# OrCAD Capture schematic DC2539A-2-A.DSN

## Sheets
1 PAGE2: size Custom
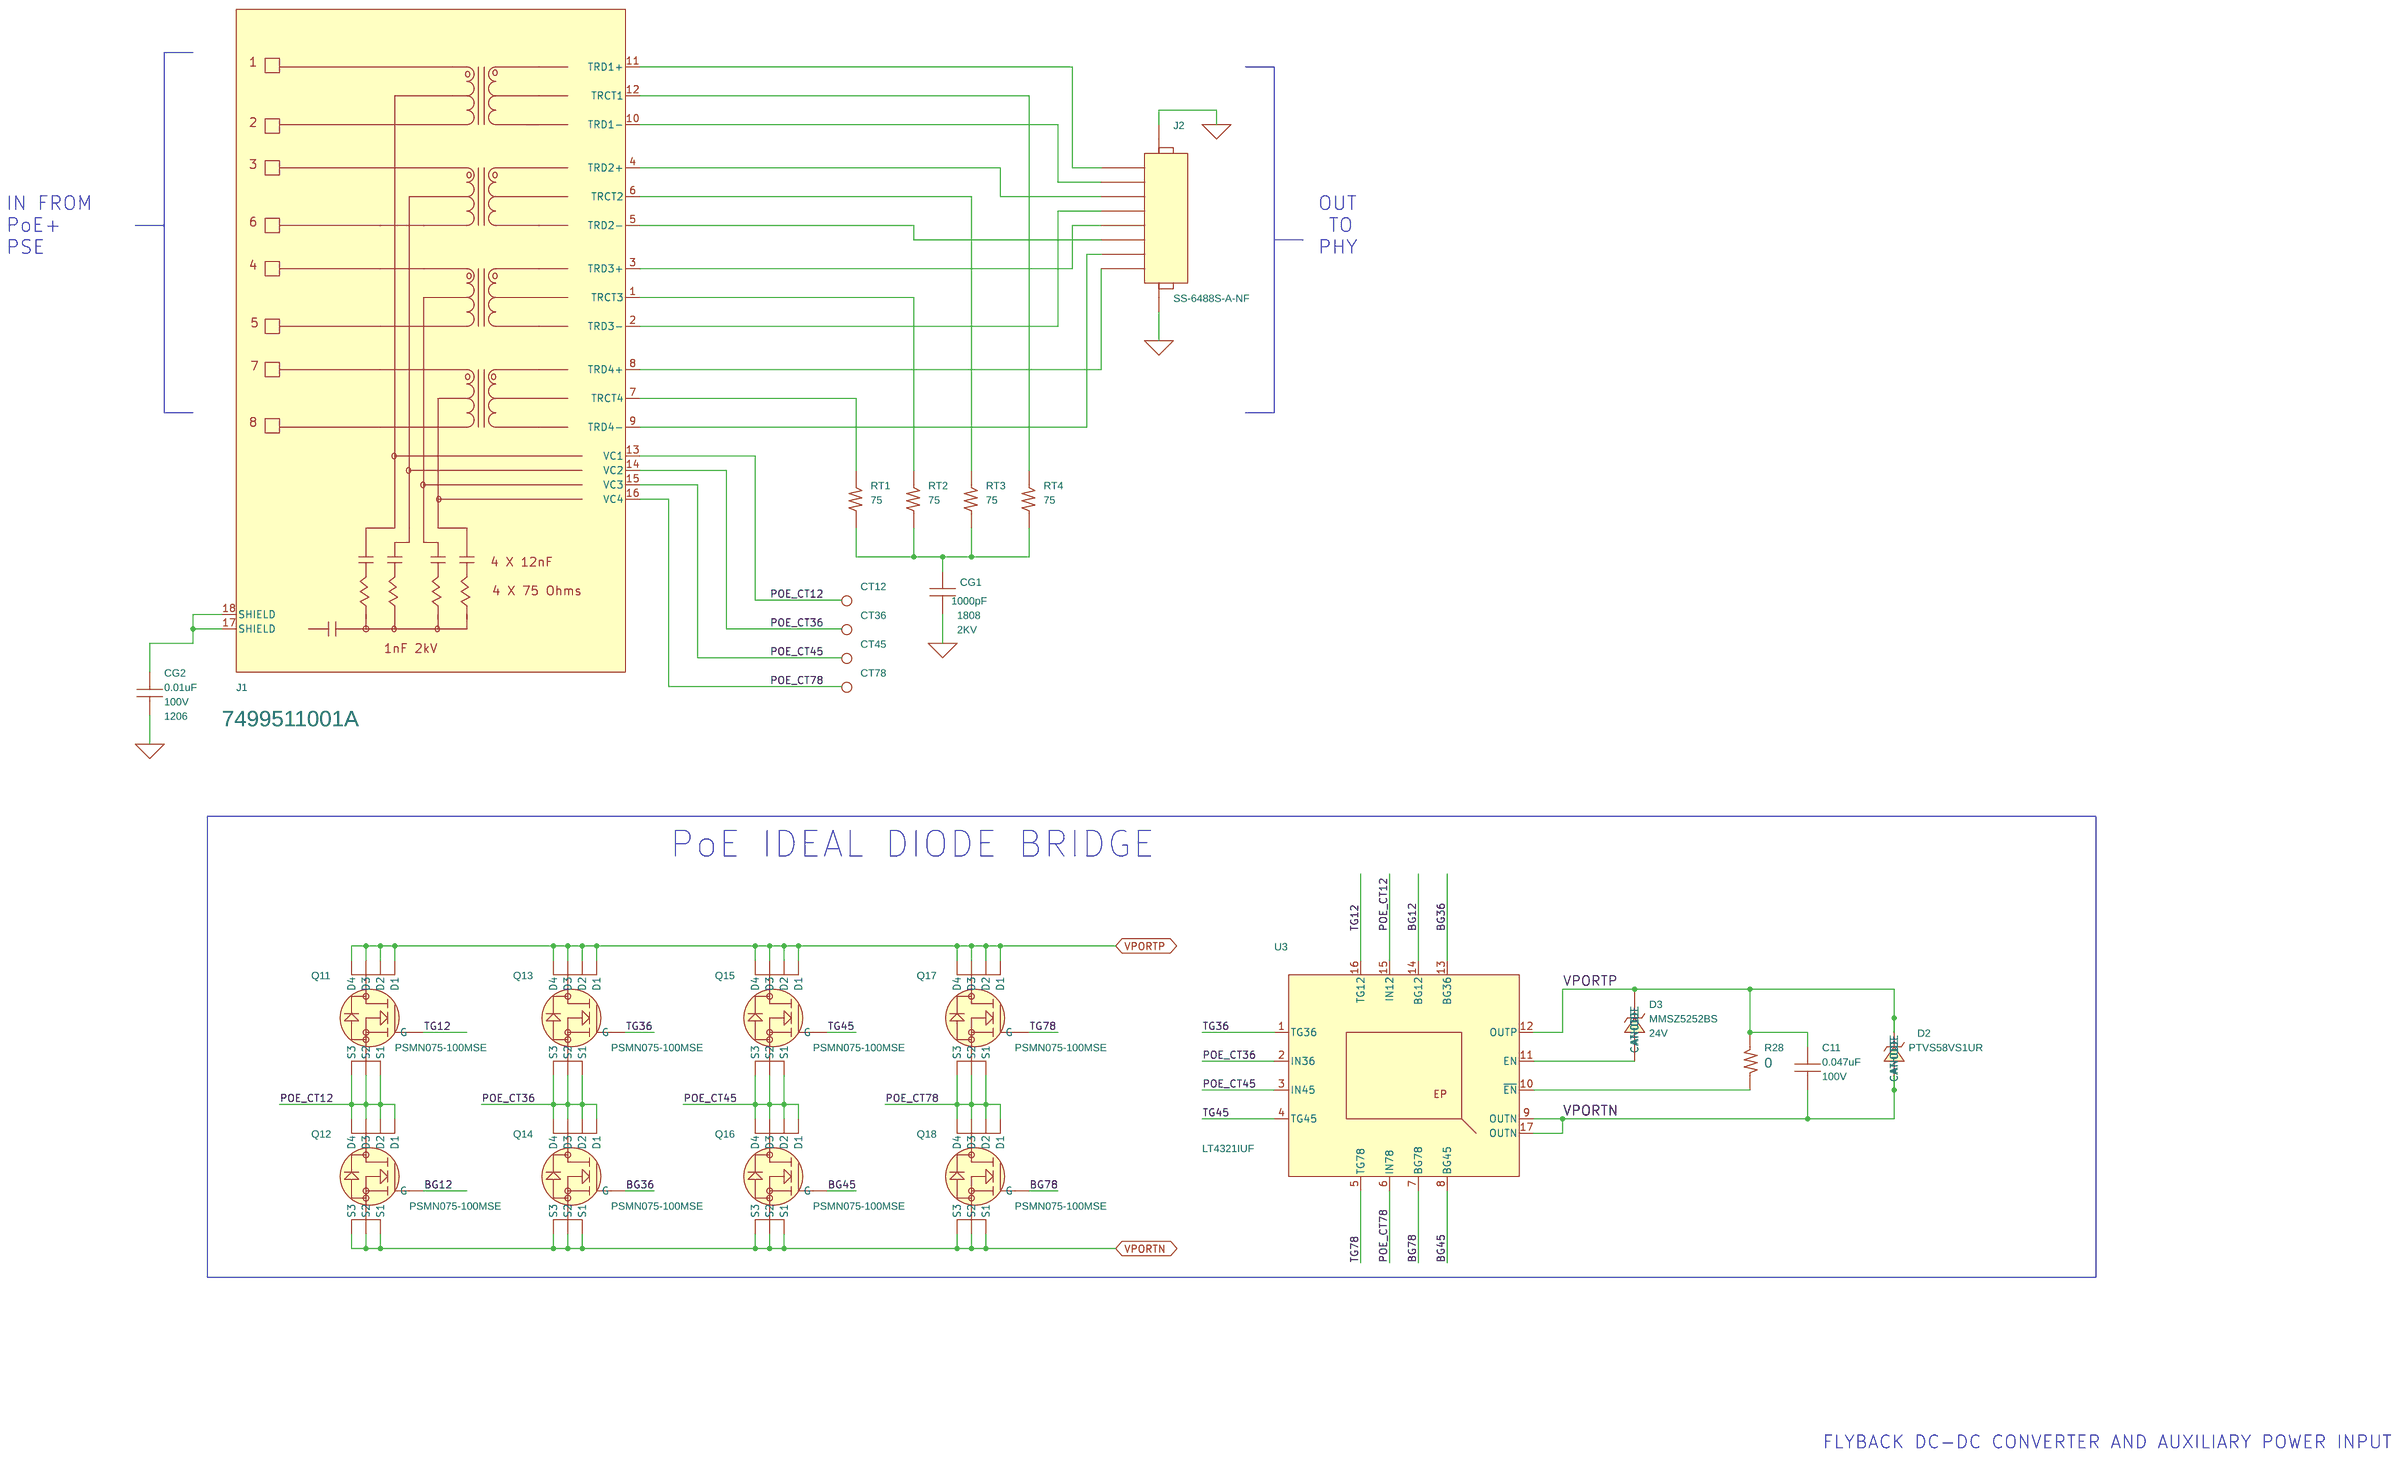
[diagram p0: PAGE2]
2 PAGE1: size Custom
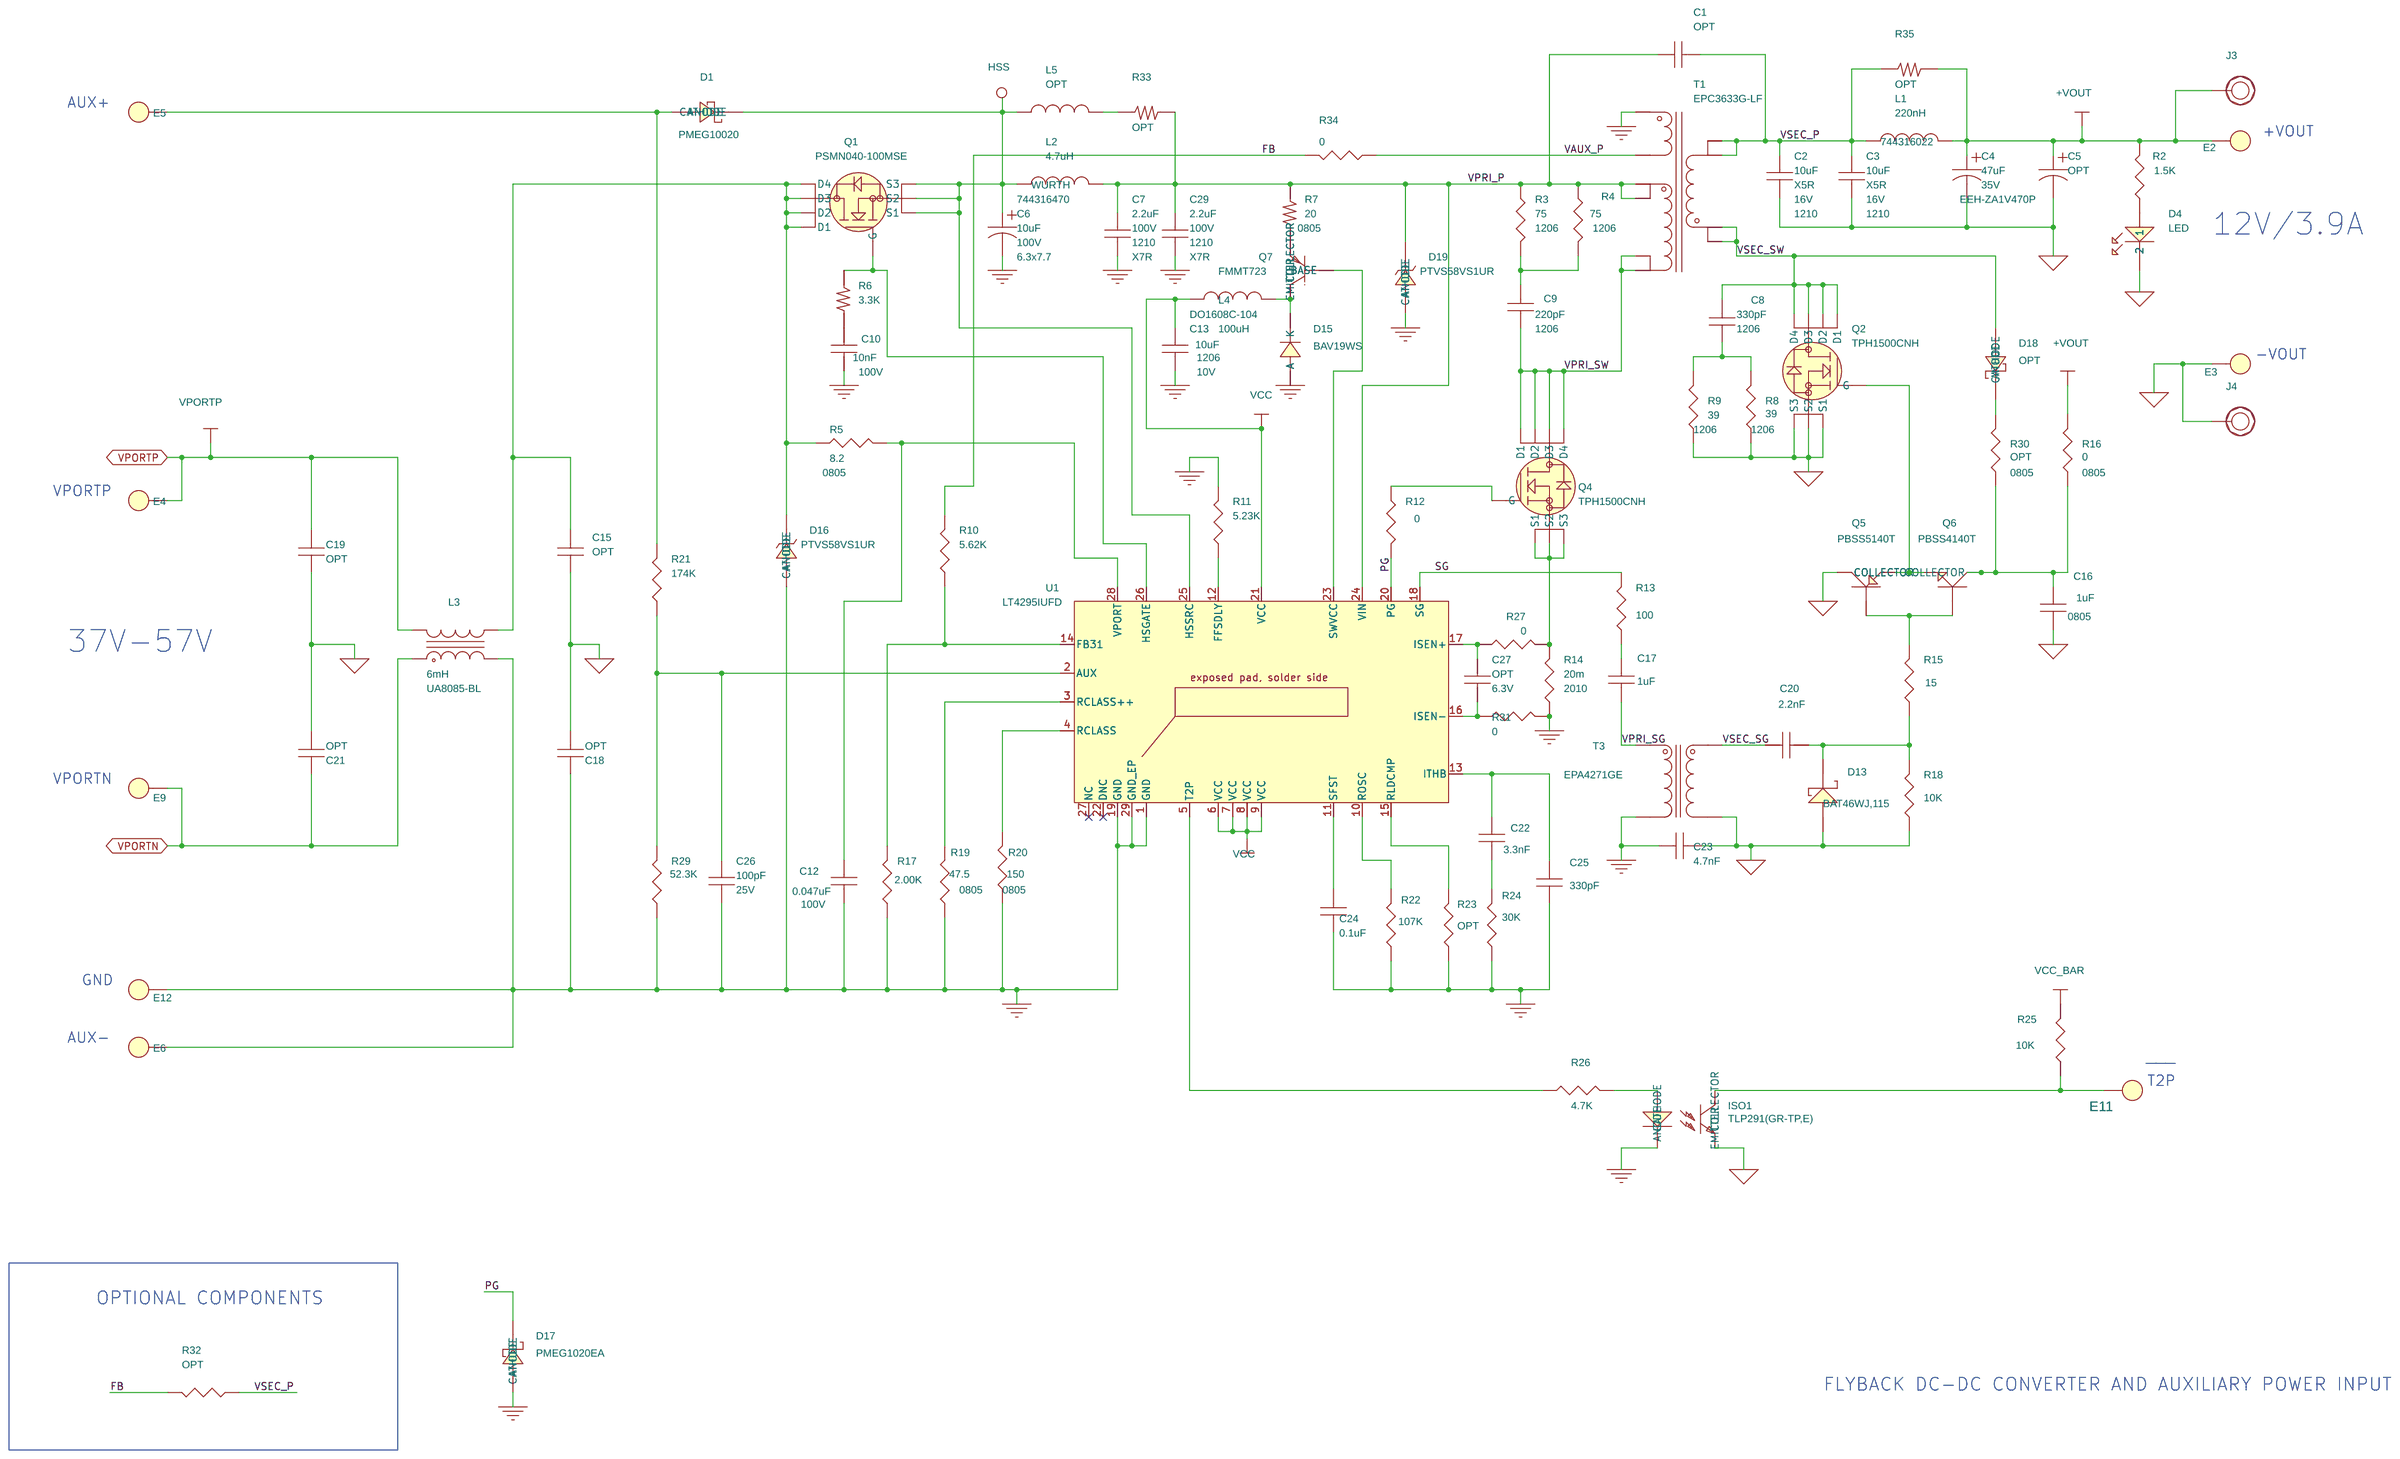
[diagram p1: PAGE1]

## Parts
sheet PAGE1
C1  OPT  [1812S]
C2  10uF  [1210]
C3  10uF  [1210]
C4  47uF  [C-EP-HVA-6.3X6.0]
C5  OPT  [C-EP-HVA-6.3X6.0]
C6  10uF  [SANYO\6.3X7.7]
C7  2.2uF  [1210]
C8  330pF  [CC1206SMALL]
C9  220pF  [CC1206SMALL]
C10  10nF  [CC0805SMALL]
C12  0.047uF  [CC0603SMALL]
C13  10uF  [CC1206SMALL]
C15  OPT  [1812S]
C16  1uF  [CC0805SMALL]
C17  1uF  [CC0603SMALL]
C18  OPT  [1812S]
C19  OPT  [1812S]
C20  2.2nF  [CC0603SMALL]
C21  OPT  [1812S]
C22  3.3nF  [CC0603SMALL]
C23  4.7nF  [1812S]
C24  0.1uF  [CC0603SMALL]
C25  330pF  [CC0603SMALL]
C26  100pF  [0402S]
C27  OPT  [0402S]
C29  2.2uF  [1210]
D1  PMEG10020  [SOD128]
D4  LED  [LED-ROHM-SML-010]
D13  BAT46WJ,115  [SOD323]
D15  BAV19WS  [SOD323]
D16  PTVS58VS1UR  [SOD123]
D17  PMEG1020EA  [SOD323]
D18  OPT  [SOD323]
D19  PTVS58VS1UR  [SOD123]
E2  PAD150-094  [PAD150-094]
E3  PAD150-094  [PAD150-094]
E4  PAD150-094  [PAD150-094]
E5  PAD150-094  [PAD150-094]
E6  PAD150-094  [PAD150-094]
E9  PAD150-094  [PAD150-094]
E11  PAD150-094  [PAD150-094]
E12  PAD150-094  [PAD150-094]
HSS  E-SMT-060  [SMTP]
ISO1  TLP291(GR-TP,E)  [SO4]
J3  Banana Jack  [KEYSTONE-575-4]
J4  Banana Jack  [KEYSTONE-575-4]
L1  220nH  [IND_WE_EATON_5030]
L2  4.7uH  [IND_WE_EATON_5030]
L3  6mH  [CMC-CC-CL]
L4  100uH  [IND-COILCRAFT-DO1608C]
L5  OPT  [CC0805SMALL]
Q1  PSMN040-100MSE  [POWERPAK1212]
Q2  TPH1500CNH  [SO8-POWERPAK]
Q4  TPH1500CNH  [SO8-POWERPAK]
Q5  PBSS5140T  [SOT23]
Q6  PBSS4140T  [SOT23]
Q7  FMMT723  [SOT23]
R2  1.5K  [CC0805SMALL]
R3  75  [CC1206SMALL]
R4  75  [CC1206SMALL]
R5  8.2  [CC0805SMALL]
R6  3.3K  [CC0603SMALL]
R7  20  [CC0805SMALL]
R8  39  [CC1206SMALL]
R9  39  [CC1206SMALL]
R10  5.62K  [CC0603SMALL]
R11  5.23K  [CC0603SMALL]
R12  0  [CC0603SMALL]
R13  100  [CC0603SMALL]
R14  20m  [2010]
R15  15  [CC0603SMALL]
R16  0  [CC0805SMALL]
R17  2.00K  [CC0603SMALL]
R18  10K  [CC0603SMALL]
R19  47.5  [CC0805SMALL]
R20  150  [CC0805SMALL]
R21  174K  [CC0603SMALL]
R22  107K  [CC0603SMALL]
R23  OPT  [CC0603SMALL]
R24  30K  [CC0603SMALL]
R25  10K  [CC0603SMALL]
R26  4.7K  [CC0603SMALL]
R27  0  [0402S]
R29  52.3K  [CC0603SMALL]
R30  OPT  [CC0805SMALL]
R31  0  [0402S]
R32  OPT  [1812S]
R33  OPT  [CC0805SMALL]
R34  0  [CC0603SMALL]
R35  OPT  [2010]
T1  EPC3633G-LF  [TRANS-PCA-EPC3472]
T3  EPA4271GE  [TRANSFORMER/PULSE/PE-68386]
U1  LT4295IUFD  [QFN28UFD-4X5]
sheet PAGE2
C11  0.047uF  [CC0603SMALL]
CG1  1000pF  [1808]
CG2  0.01uF  [CC1206SMALL]
CT12  E-SMT-060  [SMTP]
CT36  E-SMT-060  [SMTP]
CT45  E-SMT-060  [SMTP]
CT78  E-SMT-060  [SMTP]
D2  PTVS58VS1UR  [SOD123]
D3  MMSZ5252BS  [SOD323]
J1  7499511001A  [TRANS-WURTH-7499511001]
J2  SS-6488S-A-NF  [CON-SS7188]
Q11  PSMN075-100MSE  [POWERPAK1212]
Q12  PSMN075-100MSE  [POWERPAK1212]
Q13  PSMN075-100MSE  [POWERPAK1212]
Q14  PSMN075-100MSE  [POWERPAK1212]
Q15  PSMN075-100MSE  [POWERPAK1212]
Q16  PSMN075-100MSE  [POWERPAK1212]
Q17  PSMN075-100MSE  [POWERPAK1212]
Q18  PSMN075-100MSE  [POWERPAK1212]
R28  0  [CC0603SMALL]
RT1  75  [CC0603SMALL]
RT2  75  [CC0603SMALL]
RT3  75  [CC0603SMALL]
RT4  75  [CC0603SMALL]
U3  LT4321IUF  [QFN16UF-4X4]

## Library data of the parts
C1 = CAP-NP: 1st Part: Cap; 2nd Part Type: Cer; 5th Voltage: 2kV; 7th Size: 1812
C2 C3 = CAP-NP: 1st Part: CAP; 2nd Part Type: Cer; 3rd Tempco: X5R; 5th Voltage: 16V; 6th Tolerance: 10%; 8th Mfr: Murata
C4 = CAP: 2nd Part Type: Elec; 5th Voltage: 35V; 6th Tolerance: 20%; 7th Size: 6.3X6.0; 8th Mfr: PANASONIC; 9th Part Number: EEH-ZA1V470P
C5 = CAP: 2nd Part Type: Elec; 5th Voltage: 35V; 6th Tolerance: 20%; 7th Size: 6.3X6.0
C6 = CAP: 2nd Part Type: Elec; 5th Voltage: 100V; 6th Tolerance: 10%; 7th Size: 6.3x7.7; 8th Mfr: SUNCON; 9th Part Number: 100CE10KX
C7 C29 = CAP-NP: 1st Part: CAP; 2nd Part Type: Cer; 3rd Tempco: X7R; 5th Voltage: 100V; 6th Tolerance: 10%; 8th Mfr: Murata; 9th Part Number: GRM32ER72A225KA35
C8 C9 = CAP-NP: 1st Part: Cap; 2nd Part Type: Cer; 3rd Tempco: U2J; 5th Voltage: 630V; 6th Tolerance: 5%; 7th Size: 1206; 8th Mfr: Murata; 9th Part Number: TBD
C10 = CAP-NP: 1st Part: Cap; 2nd Part Type: Cer; 3rd Tempco: X7R; 5th Voltage: 100V; 6th Tolerance: 10%; 7th Size: 0805; 8th Mfr: TBD
C12 = CAP-NP: 1st Part: Cap; 2nd Part Type: Cer; 3rd Tempco: X7R; 5th Voltage: 100V; 6th Tolerance: 20%; 7th Size: 0603; 8th Mfr: TBD
C13 = CAP-NP: 1st Part: Cap; 2nd Part Type: Cer; 3rd Tempco: X7R; 5th Voltage: 10V; 6th Tolerance: 20%; 7th Size: 1206; 8th Mfr: Murata; 9th Part Number: GRM31CR71A106KA01L
C15 C18 C19 C21 = CAP-NP: 1st Part: Cap; 2nd Part Type: Cer; 3rd Tempco: X5R; 5th Voltage: 2KV; 6th Tolerance: 20%; 7th Size: 1812
C16 = CAP-NP: 1st Part: Cap; 2nd Part Type: Cer; 3rd Tempco: X7R; 5th Voltage: 25V; 6th Tolerance: 10%; 7th Size: 0805; 8th Mfr: TBD
C17 = CAP-NP: 1st Part: Cap; 2nd Part Type: Cer; 3rd Tempco: X7R; 5th Voltage: 25V; 6th Tolerance: 10%; 7th Size: 0603; 8th Mfr: Murata; 9th Part Number: GRM188R71E105KA12
C20 = CAP-NP: 1st Part: Cap; 2nd Part Type: Cer; 3rd Tempco: X7R; 5th Voltage: 25V; 6th Tolerance: 10%; 7th Size: 0603; 8th Mfr: Murata; 9th Part Number: GRM188R71E222KA01
C22 = CAP-NP: 1st Part: Cap; 2nd Part Type: Cer; 3rd Tempco: X7R; 5th Voltage: 25V; 6th Tolerance: 10%; 7th Size: 0603; 8th Mfr: TBD
C23 = CAP-NP: 1st Part: Cap; 2nd Part Type: Cer; 3rd Tempco: X7R; 5th Voltage: 2kV; 7th Size: 1812; 8th Mfr: Murata; 9th Part Number: GR443DR73D472KW01L
C24 = CAP-NP: 1st Part: Cap; 2nd Part Type: Cer; 3rd Tempco: X7R; 5th Voltage: 25V; 6th Tolerance: 20%; 7th Size: 0603; 8th Mfr: TBD
C25 = CAP-NP: 1st Part: Cap; 2nd Part Type: Cer; 3rd Tempco: X7R; 5th Voltage: 25V; 6th Tolerance: 10%; 7th Size: 0603; 8th Mfr: Murata; 9th Part Number: TBD
C26 = CAP-NP: 1st Part: Cap; 2nd Part Type: Cer; 3rd Tempco: X7R; 5th Voltage: 25V; 6th Tolerance: 10%; 7th Size: 0603; 8th Mfr: AVX; 9th Part Number: 0402YC101KAT2A
C27 = CAP-NP: 1st Part: Cap; 2nd Part Type: Cer; 3rd Tempco: X7R; 5th Voltage: 6.3V; 6th Tolerance: 10%; 7th Size: 0402; 8th Mfr: TBD
D1 = DIODE_SCHOTTKY_0: 1st Part: Diode; 2nd Part Type: Schottky; 5th Voltage: 100V; 8th Mfr: NXP; 9th Part Number: PMEG10020AELPX
D4 = LED_0: 1st Part: DIODE; 8th Mfr: ROHM; 9th Part Number: SML-010FTT86L
D13 = DIODE-SCHOTTKY_0: 1st Part: DIODE; 2nd Part Type: Schottky; 5th Voltage: 100; 8th Mfr: NXP
D15 = DIODE_4: 1st Part: Diode; 2nd Part Type: DIODE; 5th Voltage: 120V; 8th Mfr: DIODE INC
D16 = DIODE_ZENER_0: 1st Part: DIODE; 2nd Part Type: TVS; 5th Voltage: 60; 8th Mfr: NXP; 9th Part Number: PTVS60VS1UR
D17 = DIODE_SCHOTTKY_0: 1st Part: Diode; 2nd Part Type: Schottky; 5th Voltage: 10V; 8th Mfr: NXP
D18 = DIODE_SCHOTTKY_0: 1st Part: Diode; 2nd Part Type: DIODE INC; 5th Voltage: 30V; 8th Mfr: DIODE INC
D2 D19 = DIODE_ZENER_0: 1st Part: DIODE; 2nd Part Type: TVS; 5th Voltage: 58; 8th Mfr: NXP
E2 E3 E11 = E: 1st Part: TP; 2nd Part Type: TURRET; 7th Size: 0.094"; 8th Mfr: MILL-MAX; 9th Part Number: 2501-2-00-80-00-00-07-0
E4-E6 E9 E12 = E: TURRETS; 1st Part: TP; 2nd Part Type: TURRET; 7th Size: 0.094"; 8th Mfr: MILL-MAX; 9th Part Number: 2501-2-00-80-00-00-07-0; Part Number: MILLMAX 2501-2
CT12 CT36 CT45 CT78 HSS = E-SMT-060: 1st Part: CONN; 2nd Part Type: TP
ISO1 = OPTO_ISOLATOR-A_0: 1st Part: OPTO; 8th Mfr: TOSHIBA
J3 J4 = E-KEY-575: 1st Part: CONN; 2nd Part Type: BANANA JACK; 8th Mfr: KEYSTONE; 9th Part Number: 575-4
L1 = IND: 8th Mfr: WURTH; 9th Part Number: 744316022
L2 = IND: 8th Mfr: WURTH; 9th Part Number: 744316470
L3 = IND_3: 1st Part: IND; 2nd Part Type: CMC; 8th Mfr: COILCRAFT; 9th Part Number: UA8085-BL
L4 = IND: 8th Mfr: COILCRAFT; 9th Part Number: DO1608C-104
L5 = IND: 4th Value: 2.2uH; 8th Mfr: Murata; 9th Part Number: LQM21PN2R2NGCD
Q1 Q11-Q18 = MOSFET_N-DIODE-A-SO8: 1st Part: MOSFET; 2nd Part Type: N-CH; 5th Voltage: 100; 7th Size: LFPAK33; 8th Mfr: NXP
Q2 = MOSFET_N-DIODE-A-SO8: 1st Part: MOSFET; 2nd Part Type: N-CH; 5th Voltage: 150V; 7th Size: SUPERSO8; 8th Mfr: TOSHIBA
Q4 = MOSFET_N-DIODE-A-SO8: 1st Part: MOSFET; 2nd Part Type: N-CH; 5th Voltage: 150; 7th Size: SUPERSO8; 8th Mfr: TOSHIBA
Q5 = PNP_0: 1st Part: TRANSISTOR; 2nd Part Type: PNP; 5th Voltage: 40; 8th Mfr: NXP
Q6 = NPN_0: 1st Part: TRANSISTOR; 2nd Part Type: NPN; 5th Voltage: 40; 8th Mfr: NXP
Q7 = MMBT5401L: 1st Part: Tran; 2nd Part Type: PNP; 5th Voltage: 100V; 8th Mfr: DIODES INC
R2 R5 R16 = CR18-274JM: 1st Part: Res; 2nd Part Type: Chip; 6th Tolerance: 5%; 7th Size: 0805; 8th Mfr: TBD
R3 R4 R8 R9 = CR18-274JM: 1st Part: Res; 2nd Part Type: Chip; 6th Tolerance: 5%; 7th Size: 1206; 8th Mfr: TBD
R6 = R: 1st Part: Res; 2nd Part Type: Chip; 6th Tolerance: 5%; 7th Size: 0603; 8th Mfr: TBD
R7 R33 = R: 1st Part: Res; 2nd Part Type: Chip; 6th Tolerance: 5%; 7th Size: 0805; 8th Mfr: TBD
R10 R17 R34 = CR18-274JM: 1st Part: Res; 2nd Part Type: Chip; 6th Tolerance: 1%; 7th Size: 0603; 8th Mfr: TBD
R11-R13 R15 R18 R22 R24 R26 = CR18-274JM: 1st Part: Res; 2nd Part Type: Chip; 6th Tolerance: 5%; 7th Size: 0603; 8th Mfr: TBD
R14 = CR18-274JM: 1st Part: Res; 2nd Part Type: Chip; 6th Tolerance: 1%; 8th Mfr: TBD
R19 = CR18-274JM: 1st Part: Res; 2nd Part Type: Chip; 6th Tolerance: 1%; 7th Size: 0805; 8th Mfr: OPT
R20 = CR18-274JM: 1st Part: Res; 2nd Part Type: Chip; 6th Tolerance: 1%; 7th Size: 0805; 8th Mfr: TBD
R21 R29 = CR18-274JM: 1st Part: Res; 2nd Part Type: Chip; 6th Tolerance: 1%; 7th Size: 0603; 8th Mfr: TBD; 9th Part Number: TBD
R23 = CR18-274JM: 1st Part: Res; 2nd Part Type: Chip; 6th Tolerance: 5%; 7th Size: 0603
R25 = CR18-274JM: 1st Part: Res; 2nd Part Type: Chip; 4th Value: 47K; 6th Tolerance: 5%; 7th Size: 0603; 8th Mfr: TBD
R27 R31 = CR18-274JM: 1st Part: Res; 2nd Part Type: Chip; 6th Tolerance: 5%; 7th Size: 0402; 8th Mfr: TBD
R30 = CR18-274JM: 1st Part: Res; 2nd Part Type: Chip; 6th Tolerance: 5%; 7th Size: 0805
R32 = CR18-274JM: 1st Part: Res; 2nd Part Type: Chip; 6th Tolerance: 1%; 7th Size: 1812
R35 = R: 1st Part: Res; 2nd Part Type: Chip; 6th Tolerance: 5%; 8th Mfr: TBD
T1 = TRANS-VP3_2: XFMR, PA1477NL; 7th Part Field: Transformer; Part Number: PULSE PA1477NL
T3 = TRANS-PA0297_2: 1st Part: XFMR; 2nd Part Type: SMD GATE DRIVE; 4TH PART FIELD: PULSE,; 8th Mfr: PCA
U1 = LT4276_3: 1st Part: IC; 2nd Part Type: PD & Switcher Controller; 7th Size: QFN28; 8th Mfr: Linear Tech; 9th Part Number: LT4295
C11 = CAP-NP: 1st Part: CAP; 2nd Part Type: Cer; 3rd Tempco: X7R; 5th Voltage: 100V; 6th Tolerance: 20%; 7th Size: 0603; 8th Mfr: TBD; Voltage Rating: 100V
CG1 = CAP-NP: 1st Part: Cap; 2nd Part Type: Cer; 3rd Tempco: X7R; 5th Voltage: 2KV; 6th Tolerance: 10%; 8th Mfr: Murata; 9th Part Number: GR442QR73D102KW01L
CG2 = CAP-NP: 1st Part: CAP; 2nd Part Type: Cer; 3rd Tempco: X7R; 5th Voltage: 100V; 6th Tolerance: 20%; 7th Size: 1206; 8th Mfr: TBD; Voltage Rating: 100V
D3 = DIODE_ZENER_0: 1st Part: DIODE; 2nd Part Type: Zener; 5th Voltage: 24V; 8th Mfr: Diodes Inc; 9th Part Number: MMSZ5256BS
J1 = TRNSFMR_165P_8: 1st Part: CONN; 2nd Part Type: Integrated Jack; 8th Mfr: Wurth; 9th Part Number: 7499511001
J2 = 8_HEADER_1: 1st Part: CONN; 2nd Part Type: RJ45 Jack; 8th Mfr: Stewart Connector
R28 = R: 1st Part: Res; 2nd Part Type: Chip; 6th Tolerance: 5%; 7th Size: 0603; 8th Mfr: TBD; Size: 0603; Tolerance: 5%
RT1-RT4 = R: 1st Part: Res; 2nd Part Type: Chip; 6th Tolerance: 5%; 7th Size: 0603; 8th Mfr: AAC; 9th Part Number: CR16-750JM
U3 = LT4321_QFN_1: 1st Part: IC; 2nd Part Type: PoE Ideal Bridge Controller; 7th Size: QFN16; 8th Mfr: Linear Tech; 9th Part Number: LT4321

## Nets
GND_POWER: C6.2 C7.2 C10.2 C12.2 C13.2 C18.1 C23.1 C24.1 C25.1 C26.2 C29.2 D15.2(A) D16.2(ANODE) D17.2(ANODE) D19.2(ANODE) E6.1(A) E12.1(A) ISO1.2(CATHODE) L3.2 R11.2 R14.2 R17.1 R19.1 R20.1 R22.1 R23.1 R24.1 R29.1 R31.2 T1.5 T3.3 U1.1(GND) U1.19(GND) U1.29(GND_EP)
VCC: C13.1 L4.1 U1.6(VCC) U1.7(VCC) U1.8(VCC) U1.9(VCC) U1.21(VCC)
+VOUT: C4.1 C5.1 E2.1(A) J3.1 L1.2 R2.2 R16.2 R25.2 R35.2
BG12: Q12.4(G) U3.14(BG12)
BG36: Q14.4(G) U3.13(BG36)
BG45: Q16.4(G) U3.8(BG45)
BG78: Q18.4(G) U3.7(BG78)
FB: R10.2 R32.2 R34.2
PG: D17.1(CATHODE) R12.2 U1.20(PG)
POE_CT12: CT12.1 J1.13(VC1) Q11.1(S1) Q11.2(S2) Q11.3(S3) Q12.5(D1) Q12.6(D2) Q12.7(D3) Q12.8(D4) U3.15(IN12)
POE_CT36: CT36.1 J1.14(VC2) Q13.1(S1) Q13.2(S2) Q13.3(S3) Q14.5(D1) Q14.6(D2) Q14.7(D3) Q14.8(D4) U3.2(IN36)
POE_CT45: CT45.1 J1.15(VC3) Q15.1(S1) Q15.2(S2) Q15.3(S3) Q16.5(D1) Q16.6(D2) Q16.7(D3) Q16.8(D4) U3.3(IN45)
POE_CT78: CT78.1 J1.16(VC4) Q17.1(S1) Q17.2(S2) Q17.3(S3) Q18.5(D1) Q18.6(D2) Q18.7(D3) Q18.8(D4) U3.6(IN78)
SEC_GND: C2.2 C3.2 C4.2 C5.2 C15.1 C16.2 C18.2 C19.1 C21.2 C23.2 CG1.2 CG2.2 D4.2 D13.2 E3.1(A) ISO1.3(COLLECTOR) J2.9 J2.10 J4.1 Q2.1(S1) Q2.2(S2) Q2.3(S3) Q5.3(COLLECTOR) R8.1 R9.1 R18.1 T3.4
SG: R13.2 U1.18(SG)
TG12: Q11.4(G) U3.16(TG12)
TG36: Q13.4(G) U3.1(TG36)
TG45: Q15.4(G) U3.4(TG45)
TG78: Q17.4(G) U3.5(TG78)
VAUX_P: R34.1 T1.6
VPORTN: C11.2 C21.1 D2.2(ANODE) E9.1(A) L3.1 Q12.1(S1) Q12.2(S2) Q12.3(S3) Q14.1(S1) Q14.2(S2) Q14.3(S3) Q16.1(S1) Q16.2(S2) Q16.3(S3) Q18.1(S1) Q18.2(S2) Q18.3(S3) U3.9(OUTN) U3.17(OUTN)
VPORTP: C11.1 C19.2 D2.1(CATHODE) D3.1(CATHODE) E4.1(A) L3.4 Q11.5(D1) Q11.6(D2) Q11.7(D3) Q11.8(D4) Q13.5(D1) Q13.6(D2) Q13.7(D3) Q13.8(D4) Q15.5(D1) Q15.6(D2) Q15.7(D3) Q15.8(D4) Q17.5(D1) Q17.6(D2) Q17.7(D3) Q17.8(D4) R28.1 U3.12(OUTP)
VPRI_P: C1.1 C7.1 C29.1 D19.1(CATHODE) L2.2 R3.2 R4.2 R7.1 R33.2 T1.1 T1.2 U1.24(VIN)
VPRI_SG: C17.2 T3.1
VPRI_SW: C9.1 Q4.5(D1) Q4.6(D2) Q4.7(D3) Q4.8(D4) T1.3 T1.4
VSEC_P: C1.2 C2.1 C3.1 L1.1 R32.1 R35.1 T1.7 T1.8
VSEC_SG: C20.1 T3.6
VSEC_SW: C8.2 D18.2(ANODE) Q2.5(D1) Q2.6(D2) Q2.7(D3) Q2.8(D4) T1.11 T1.12
N16777712: C16.1 Q6.3(COLLECTOR) R16.1 R30.1
N16777792: C22.2 R24.2
N16777907: C20.2 D13.1 R15.1 R18.2
N16777983: C9.2 R3.1 R4.1
N16777990: Q5.1 Q6.1 R15.2
N16778156: C6.1 D1.1(CATHODE) HSS.1 L2.1 L5.1 Q1.1(S1) Q1.2(S2) Q1.3(S3) U1.25(HSSRC)
N16778195: C22.1 C25.2 U1.13(ITHB)
N16778197: C8.1 R8.2 R9.2
N16778751: Q2.4(G) Q5.2 Q6.2
N16778819: R10.1 R17.2 U1.14(FB31)
N16778917: C17.1 R13.1
N16793422: C15.2 D16.1(CATHODE) L3.3 Q1.5(D1) Q1.6(D2) Q1.7(D3) Q1.8(D4) R5.1
N16835353: R11.1 U1.12(FFSDLY)
N16854739: Q1.4(G) R6.1 U1.26(HSGATE)
N16871044: C12.1 R5.2 U1.28(VPORT)
N16895058: R19.2 U1.3(RCLASS++)
N16896043: R20.2 U1.4(RCLASS)
N16911319: R23.2 U1.15(RLDCMP)
N16912256: R22.2 U1.10(ROSC)
N16913595: C24.2 U1.11(SFST)
N16989975: Q4.1(S1) Q4.2(S2) Q4.3(S3) R14.1 R27.2
N17153674: Q4.4(G) R12.1
N17470232: C27.1 R27.1 U1.17(ISEN+)
N17471634: C27.2 R31.1 U1.16(ISEN-)
N17491181: Q7.1(BASE) U1.23(SWVCC)
N17674405: D15.1(K) L4.2 Q7.3(COLLECTOR)
N17832538: J1.4(TRD2+) J2.3
N17832540: J1.6(TRCT2) RT3.1
N17832548: CG2.1 J1.17(SHIELD) J1.18(SHIELD)
N17832623: CG1.1 RT1.2 RT2.2 RT3.2 RT4.2
N17832635: J1.3(TRD3+) J2.5
N17832687: J1.9(TRD4-) J2.7
N17832689: J1.2(TRD3-) J2.4
N17832691: J1.8(TRD4+) J2.8
N17832695: J1.7(TRCT4) RT1.1
N17832697: J1.1(TRCT3) RT2.1
N17832701: J1.12(TRCT1) RT4.1
N17832723: J1.11(TRD1+) J2.1
N17832729: J1.10(TRD1-) J2.2
N17832735: J1.5(TRD2-) J2.6
N17867250: D3.2(ANODE) U3.11(EN)
N17867273: R28.2 U3.10(~{EN})
N18283175: D18.1(CATHODE) R30.2
N18441272: C26.1 R21.1 R29.2 U1.2(AUX)
N18707029: L5.2 R33.1
N18841108: D1.2(ANODE) E5.1(A) R21.2
N18854065: ISO1.1(ANODE) R26.2
N18854069: E11.1(A) ISO1.4(EMITTER) R25.1
N18854146: R26.1 U1.5(T2P)
N19068250: C10.1 R6.2
N19068251: Q7.2(EMITTER) R7.2
N19068252: D4.1 R2.1

Not connected (* = marked no-connect by the designer): U1 22(DNC)* 27(NC)*

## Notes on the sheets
sheet 1
- IN FROM
  PoE+
  PSE
- OUT
   TO
  PHY
- PoE IDEAL DIODE BRIDGE
- FLYBACK DC-DC CONVERTER AND AUXILIARY POWER INPUT
sheet 2
- AUX+
- +VOUT
- 12V/3.9A
- -VOUT
- VPORTP
- 37V-57V
- VPORTN
- GND
- AUX-
- ___
- T2P
- OPTIONAL COMPONENTS
- FLYBACK DC-DC CONVERTER AND AUXILIARY POWER INPUT
